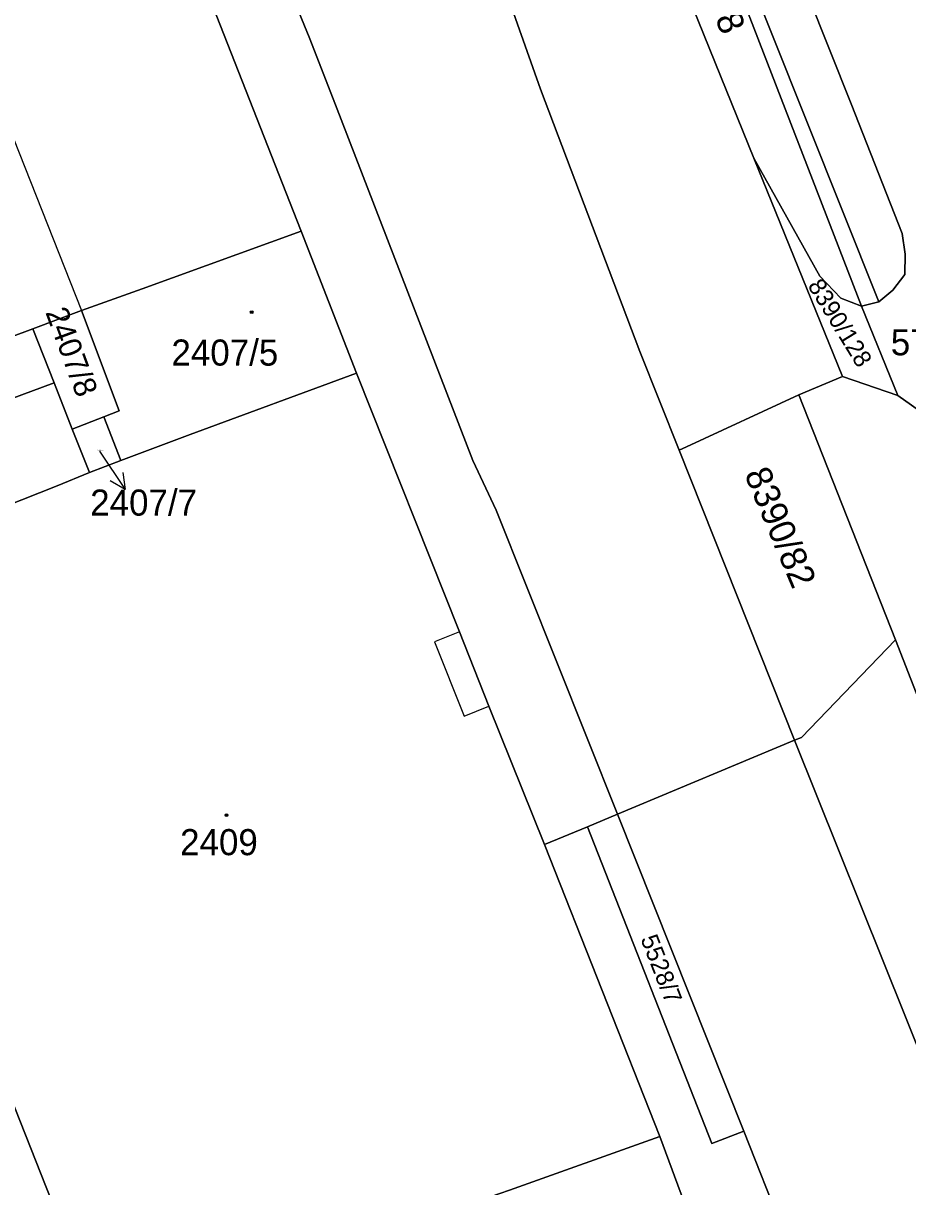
# Model space of a CAD drawing. Extents: x -596233 to -595156, y -1161235 to -1159375.
# Drawn here: x -595514 to -595456.5, y -1160472 to -1160396.3 of the extents above; entities that cross this region are included whole.
import ezdxf

# ---------------------------------------------------------------- set-up
doc = ezdxf.new("R2010")
doc.units = 0
for name, color, linetype in [('KN_CAR_KR', 7, 'Continuous'), ('KN_KULTURY', 7, 'Continuous'), ('KN_PARC_CIS_POM', 7, 'Continuous'), ('KN_PARC_CIS_POZ', 7, 'Continuous'), ('KN_PARC_CIS_STAV', 7, 'Continuous'), ('KN_PARC_PLOCHA', 7, 'Continuous'), ('PARC_C_SIPKA', 7, 'Continuous'), ('parcely_l', 7, 'Continuous')]:
    doc.layers.add(name, color=color, linetype=linetype)

msp = doc.modelspace()

# ---------------------------------------------------------------- linework, layer by layer
at = {"layer": 'KN_CAR_KR'}
for points in [[(-595515.8, -1160401), (-595510.25, -1160415)], [(-595485.65, -1160435.91), (-595487.28, -1160436.56)], [(-595487.28, -1160436.56), (-595485.35, -1160441.4)], [(-595485.35, -1160441.4), (-595483.73, -1160440.75)]]:
    msp.add_lwpolyline(points, dxfattribs=at)
at = {"layer": 'KN_KULTURY'}
for centre, radius in [((-595499.17, -1160415.1), 0.09), ((-595499.17, -1160415.1), 0.0398), ((-595500.81, -1160447.86), 0.09), ((-595500.81, -1160447.86), 0.0398)]:
    msp.add_circle(centre, radius, dxfattribs=at)
at = {"layer": 'KN_PARC_PLOCHA'}
for points in [[(-595516.45, -1160308.75), (-595513.74, -1160315.29), (-595511.56, -1160320.72), (-595509.16, -1160326.51), (-595491.65, -1160371.85), (-595489.02, -1160378.2), (-595482.37, -1160394.93), (-595480.37, -1160400.59), (-595473.92, -1160417.66), (-595471.36, -1160424.09), (-595463.86, -1160442.98), (-595475.37, -1160447.79), (-595483.26, -1160428), (-595484.78, -1160424.75), (-595493.72, -1160401.6), (-595495.44, -1160397.2), (-595497.53, -1160392.05), (-595510.34, -1160359.58), (-595514.98, -1160347.86)], [(-595514.98, -1160347.86), (-595510.34, -1160359.58), (-595497.53, -1160392.05), (-595495.44, -1160397.2), (-595493.72, -1160401.6), (-595484.78, -1160424.75), (-595483.26, -1160428), (-595475.37, -1160447.79), (-595477.33, -1160448.61), (-595480.11, -1160449.77), (-595483.73, -1160440.75), (-595485.65, -1160435.91), (-595492.34, -1160419.07), (-595495.94, -1160409.83), (-595504.35, -1160388.43), (-595506.07, -1160384.36), (-595513.26, -1160365.9), (-595516.77, -1160357.02)], [(-595460.91, -1160378.21), (-595449.82, -1160405.93), (-595451.62, -1160406.6), (-595448.74, -1160414.03), (-595448.23, -1160414.9), (-595447.49, -1160415.6), (-595446.81, -1160416), (-595445.63, -1160421.23), (-595448.87, -1160421.96), (-595451.7, -1160423.13), (-595452.68, -1160423.67), (-595457.13, -1160420.53), (-595459.49, -1160414.7), (-595458.37, -1160414.43), (-595457.45, -1160413.66), (-595456.67, -1160412.65), (-595456.65, -1160411.33), (-595456.84, -1160409.98), (-595460.16, -1160401.53), (-595471.44, -1160373.21)], [(-595427.75, -1160533.04), (-595463.86, -1160442.98), (-595463.4, -1160442.79), (-595457.27, -1160436.43), (-595450.45, -1160453.97), (-595440.26, -1160479.52)], [(-595459.53, -1160487.7), (-595467.14, -1160468.43), (-595475.37, -1160447.79), (-595463.86, -1160442.98), (-595427.75, -1160533.04)], [(-595470.28, -1160475.11), (-595472.61, -1160468.77), (-595480.11, -1160449.77), (-595477.33, -1160448.61), (-595469.24, -1160469.23), (-595467.14, -1160468.43), (-595459.53, -1160487.7)]]:
    msp.add_lwpolyline(points, dxfattribs=at)
for points in [[(-595495.94, -1160409.83), (-595506.3, -1160413.57), (-595510.25, -1160415), (-595513.41, -1160416.18), (-595526.34, -1160421.01), (-595528.55, -1160421.83), (-595531.56, -1160413.81), (-595538.67, -1160416.45), (-595540.42, -1160410.3), (-595540.67, -1160409.65), (-595544.41, -1160411.03), (-595548.63, -1160400), (-595554.01, -1160386.51), (-595548.32, -1160384.42), (-595550.03, -1160379.76), (-595536.58, -1160374.72), (-595533.85, -1160373.69), (-595527.65, -1160371.34), (-595522.87, -1160369.54), (-595513.26, -1160365.9), (-595506.07, -1160384.36), (-595504.35, -1160388.43)], [(-595471.83, -1160372.22), (-595471.44, -1160373.21), (-595460.16, -1160401.53), (-595456.84, -1160409.98), (-595456.65, -1160411.33), (-595456.67, -1160412.65), (-595457.45, -1160413.66), (-595458.37, -1160414.43), (-595463.04, -1160402.69), (-595474.52, -1160373.9), (-595476.59, -1160370.55), (-595477.93, -1160367.21), (-595475.58, -1160366.42), (-595471.94, -1160372.26)], [(-595476.59, -1160370.55), (-595475.81, -1160372.49), (-595459.49, -1160414.7), (-595460.84, -1160414.19), (-595462.2, -1160412.76), (-595466.5, -1160405.07), (-595475.5, -1160382.8), (-595482.61, -1160368.91), (-595482.66, -1160368.81), (-595478.53, -1160367.41)], [(-595466.5, -1160405.07), (-595460.73, -1160419.28), (-595463.58, -1160420.48), (-595470.88, -1160423.87), (-595471.36, -1160424.09), (-595473.92, -1160417.66), (-595480.37, -1160400.59), (-595482.37, -1160394.93), (-595489.02, -1160378.2), (-595491.65, -1160371.85), (-595483.88, -1160369.22), (-595482.66, -1160368.81), (-595482.61, -1160368.91), (-595475.5, -1160382.8)], [(-595458.37, -1160414.43), (-595459.49, -1160414.7), (-595475.81, -1160372.49), (-595476.59, -1160370.55), (-595474.52, -1160373.9), (-595463.04, -1160402.69)], [(-595459.49, -1160414.7), (-595457.13, -1160420.53), (-595460.73, -1160419.28), (-595466.5, -1160405.07), (-595462.2, -1160412.76), (-595460.84, -1160414.19)], [(-595492.34, -1160419.07), (-595503.18, -1160423.06), (-595507.69, -1160424.76), (-595508.79, -1160421.91), (-595507.79, -1160421.52), (-595510.25, -1160415), (-595506.3, -1160413.57), (-595495.94, -1160409.83)], [(-595508.79, -1160421.91), (-595510.84, -1160422.72), (-595512.03, -1160419.7), (-595513.41, -1160416.18), (-595510.25, -1160415), (-595507.79, -1160421.52)], [(-595512.03, -1160419.7), (-595525.01, -1160424.53), (-595535.01, -1160428.25), (-595535.7, -1160426.39), (-595536.31, -1160424.73), (-595528.55, -1160421.83), (-595526.34, -1160421.01), (-595513.41, -1160416.18)], [(-595510.84, -1160422.72), (-595509.73, -1160425.53), (-595511.82, -1160426.4), (-595528.05, -1160432.83), (-595508.83, -1160481.48), (-595512.47, -1160482.74), (-595515.77, -1160474.76), (-595519.03, -1160466.88), (-595535.01, -1160428.25), (-595525.01, -1160424.53), (-595512.03, -1160419.7)], [(-595480.11, -1160449.77), (-595472.61, -1160468.77), (-595482.39, -1160472.26), (-595486.17, -1160473.58), (-595492.56, -1160475.81), (-595508.83, -1160481.48), (-595528.05, -1160432.83), (-595511.82, -1160426.4), (-595509.73, -1160425.53), (-595507.69, -1160424.76), (-595503.18, -1160423.06), (-595492.34, -1160419.07), (-595485.65, -1160435.91), (-595483.73, -1160440.75)], [(-595457.13, -1160420.53), (-595452.68, -1160423.67), (-595454.14, -1160424.99), (-595454.84, -1160426.07), (-595455.1, -1160426.47), (-595455.14, -1160426.59), (-595455.63, -1160428.18), (-595455.9, -1160430.15), (-595455.46, -1160432.53), (-595443.78, -1160461.9), (-595443.74, -1160462.31), (-595442.58, -1160465.95), (-595437.71, -1160482.89), (-595435.02, -1160492.76), (-595440.26, -1160479.52), (-595450.45, -1160453.97), (-595457.27, -1160436.43), (-595463.58, -1160420.48), (-595460.73, -1160419.28)], [(-595457.27, -1160436.43), (-595463.4, -1160442.79), (-595463.86, -1160442.98), (-595471.36, -1160424.09), (-595470.88, -1160423.87), (-595463.58, -1160420.48)], [(-595507.69, -1160424.76), (-595509.73, -1160425.53), (-595510.84, -1160422.72), (-595508.79, -1160421.91)], [(-595467.14, -1160468.43), (-595469.24, -1160469.23), (-595477.33, -1160448.61), (-595475.37, -1160447.79)], [(-595469.16, -1160477.68), (-595478.93, -1160481.06), (-595482.76, -1160482.37), (-595486.17, -1160473.58), (-595482.39, -1160472.26), (-595472.61, -1160468.77), (-595470.28, -1160475.11), (-595470.14, -1160475.05)]]:
    msp.add_lwpolyline(points, close=True, dxfattribs=at)
at = {"layer": 'PARC_C_SIPKA'}
for points in [[(-595509.07, -1160424.15), (-595507.4098, -1160426.6488)], [(-595507.5468, -1160425.5391), (-595507.4098, -1160426.6488), (-595508.3797, -1160426.0925)]]:
    msp.add_lwpolyline(points, dxfattribs=at)
at = {"layer": 'parcely_l'}
for points in [[(-595475.37, -1160447.79), (-595483.26, -1160428), (-595484.78, -1160424.75), (-595493.72, -1160401.6), (-595495.44, -1160397.2), (-595497.53, -1160392.05), (-595510.34, -1160359.58), (-595514.98, -1160347.86), (-595515.95, -1160345.24), (-595520.05, -1160335.27), (-595522.38, -1160329.79), (-595526.04, -1160320.13), (-595529.79, -1160310.64), (-595530.84, -1160308.18), (-595535.89, -1160295.48), (-595538.65, -1160292), (-595541.32, -1160290.37), (-595543.78, -1160289.37)], [(-595513.26, -1160365.9), (-595506.07, -1160384.36), (-595504.35, -1160388.43), (-595495.94, -1160409.83)], [(-595466.5, -1160405.07), (-595475.5, -1160382.8), (-595482.61, -1160368.91), (-595482.66, -1160368.81)], [(-595476.59, -1160370.55), (-595475.81, -1160372.49), (-595459.49, -1160414.7)], [(-595476.59, -1160370.55), (-595474.52, -1160373.9), (-595463.04, -1160402.69), (-595458.37, -1160414.43)], [(-595471.36, -1160424.09), (-595473.92, -1160417.66), (-595480.37, -1160400.59), (-595482.37, -1160394.93), (-595489.02, -1160378.2), (-595491.65, -1160371.85)], [(-595458.37, -1160414.43), (-595457.45, -1160413.66), (-595456.67, -1160412.65), (-595456.65, -1160411.33), (-595456.84, -1160409.98), (-595460.16, -1160401.53), (-595471.44, -1160373.21), (-595471.83, -1160372.22)], [(-595459.49, -1160414.7), (-595460.84, -1160414.19), (-595462.2, -1160412.76), (-595466.5, -1160405.07)], [(-595460.73, -1160419.28), (-595466.5, -1160405.07)], [(-595510.25, -1160415), (-595506.3, -1160413.57), (-595495.94, -1160409.83)], [(-595495.94, -1160409.83), (-595492.34, -1160419.07)], [(-595513.41, -1160416.18), (-595510.25, -1160415)], [(-595510.25, -1160415), (-595507.79, -1160421.52), (-595508.79, -1160421.91)], [(-595459.49, -1160414.7), (-595458.37, -1160414.43)], [(-595457.13, -1160420.53), (-595459.49, -1160414.7)], [(-595513.41, -1160416.18), (-595526.34, -1160421.01), (-595528.55, -1160421.83)], [(-595512.03, -1160419.7), (-595513.41, -1160416.18)], [(-595535.01, -1160428.25), (-595525.01, -1160424.53), (-595512.03, -1160419.7)], [(-595510.84, -1160422.72), (-595512.03, -1160419.7)], [(-595507.69, -1160424.76), (-595503.18, -1160423.06), (-595492.34, -1160419.07)], [(-595492.34, -1160419.07), (-595485.65, -1160435.91), (-595483.73, -1160440.75), (-595480.11, -1160449.77)], [(-595463.58, -1160420.48), (-595460.73, -1160419.28)], [(-595460.73, -1160419.28), (-595457.13, -1160420.53)], [(-595471.36, -1160424.09), (-595470.88, -1160423.87), (-595463.58, -1160420.48)], [(-595457.27, -1160436.43), (-595463.58, -1160420.48)], [(-595452.68, -1160423.67), (-595457.13, -1160420.53)], [(-595508.79, -1160421.91), (-595510.84, -1160422.72)], [(-595507.69, -1160424.76), (-595508.79, -1160421.91)], [(-595510.84, -1160422.72), (-595509.73, -1160425.53)], [(-595463.86, -1160442.98), (-595471.36, -1160424.09)], [(-595509.73, -1160425.53), (-595507.69, -1160424.76)], [(-595508.83, -1160481.48), (-595528.05, -1160432.83), (-595511.82, -1160426.4), (-595509.73, -1160425.53)], [(-595457.27, -1160436.43), (-595463.4, -1160442.79), (-595463.86, -1160442.98)], [(-595435.02, -1160492.76), (-595440.26, -1160479.52), (-595450.45, -1160453.97), (-595457.27, -1160436.43)], [(-595475.37, -1160447.79), (-595463.86, -1160442.98)], [(-595463.86, -1160442.98), (-595427.75, -1160533.04), (-595416.28, -1160564.16), (-595409.37, -1160584.4), (-595399.34, -1160612.47), (-595394.62, -1160628.27), (-595372.46, -1160708.61), (-595368.77, -1160707.68)], [(-595475.37, -1160447.79), (-595477.33, -1160448.61)], [(-595467.14, -1160468.43), (-595475.37, -1160447.79)], [(-595480.11, -1160449.77), (-595477.33, -1160448.61)], [(-595477.33, -1160448.61), (-595469.24, -1160469.23), (-595467.14, -1160468.43)], [(-595480.11, -1160449.77), (-595472.61, -1160468.77)], [(-595472.61, -1160468.77), (-595482.39, -1160472.26), (-595486.17, -1160473.58)], [(-595469.16, -1160477.68), (-595470.14, -1160475.05), (-595470.28, -1160475.11), (-595472.61, -1160468.77)], [(-595467.14, -1160468.43), (-595459.53, -1160487.7), (-595458.09, -1160491.24)]]:
    msp.add_lwpolyline(points, dxfattribs=at)

# ---------------------------------------------------------------- texts
at = {"layer": 'KN_PARC_CIS_POM'}
msp.add_text('2407/7', height=0.1, dxfattribs=at).set_placement((-595509.2033, -1160424.15))
at = {"layer": 'KN_PARC_CIS_POZ'}
for s, height, rotation, p in [('8390/88', 1.7, 292.352166, (-595471.685, -1160389.5392)), ('8390/128', 1.14, 301.434807, (-595463.0291, -1160413.3714)), ('2407/8', 1.47, 290.341638, (-595512.6078, -1160415.1048)), ('8390/82', 1.7, 292.80105, (-595467.136, -1160425.6362)), ('5528/7', 1.14, 291.373336, (-595473.8871, -1160455.9022))]:
    msp.add_text(s, height=height, rotation=rotation, dxfattribs=at).set_placement(p)
for s, p in [('5770/23', (-595457.5866, -1160417.91)), ('2407/7', (-595509.6766, -1160428.35))]:
    msp.add_text(s, height=1.7, dxfattribs=at).set_placement(p)
at = {"layer": 'KN_PARC_CIS_STAV'}
for s, p in [('2407/5', (-595504.3916, -1160418.58)), ('2409', (-595503.8266, -1160450.46))]:
    msp.add_text(s, height=1.7, dxfattribs=at).set_placement(p)

doc.saveas('drawing.dxf')
